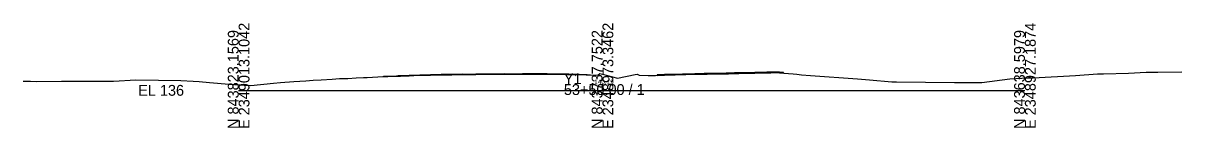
# Model space of a CAD drawing. Extents: x -26 to 2349090, y -10 to 844481.
# Drawn here: x 2300 to 2600, y -9.7 to 17.4 of the extents above; entities that cross this region are included whole.
import ezdxf

# ---------------------------------------------------------------- set-up
doc = ezdxf.new("R2010")
doc.units = 0
for name, color, linetype in [('Exist Cross Section Cell', 7, 'Continuous'), ('Exist XS Center Line Elevation Label', 7, 'Continuous'), ('Exist XS Ground Line', 7, 'Continuous'), ('Prop CMT Pvmt Surface', 7, 'Continuous'), ('Prop XS Earthwork Shape', 7, 'Continuous')]:
    doc.layers.add(name, color=color, linetype=linetype)

msp = doc.modelspace()

# ---------------------------------------------------------------- linework, layer by layer
at = {"layer": 'Exist Cross Section Cell'}
for p, q in [((2355.79, 0), (2450, 0)), ((2450, 0), (2450, 1.6)), ((2450, 0), (2559.37, 0))]:
    msp.add_line(p, q, dxfattribs=at)
at = {"layer": 'Exist XS Ground Line'}
msp.add_lwpolyline([(2300, 2.37), (2301.94, 2.36), (2303.36, 2.33), (2309.93, 2.39), (2311.19, 2.41), (2316.69, 2.37), (2317.92, 2.39), (2323.36, 2.41), (2329.14, 2.73), (2335.04, 2.67), (2340.85, 2.58), (2343.98, 2.38), (2345.54, 2.27), (2348.25, 2.07), (2353.37, 1.57), (2358.94, 1.27), (2364.8, 1.86), (2366.6, 2.06), (2370.08, 2.28), (2373.15, 2.49), (2375.07, 2.63), (2377.18, 2.73), (2380.01, 2.93), (2381.94, 3.03), (2382.69, 3.04), (2383.08, 3.05), (2384.09, 3.07), (2386.23, 3.21), (2388.16, 3.32), (2389.06, 3.35), (2391.87, 3.46), (2394.39, 3.57), (2396.65, 3.66), (2397.13, 3.68), (2397.7, 3.69), (2399.22, 3.74), (2399.91, 3.76), (2401.15, 3.82), (2402.69, 3.89), (2403.7, 3.92), (2405.44, 3.97), (2407.2, 4.01), (2408.2, 4.03), (2409.6, 4.03), (2410.95, 4.04), (2412.41, 4.08), (2413.7, 4.1), (2415.54, 4.1), (2416.44, 4.1), (2417.22, 4.11), (2419.17, 4.15), (2419.56, 4.15), (2421.47, 4.16), (2421.95, 4.16), (2422.36, 4.17), (2424.69, 4.21), (2427.45, 4.18), (2429.31, 4.2), (2430.29, 4.21), (2430.72, 4.21), (2432.52, 4.21), (2432.94, 4.21), (2433.31, 4.21), (2435.7, 4.21), (2437.83, 4.17), (2438.69, 4.16), (2439.19, 4.15), (2440.6, 4.13), (2441.24, 4.12), (2442.94, 4.09), (2443.95, 4.08), (2445.75, 4.02), (2446.85, 4), (2448.81, 3.97), (2449.31, 4.38), (2450, 4.19), (2453.86, 3.13), (2458.46, 4.12), (2458.99, 4.22), (2459.52, 3.96), (2461.8, 3.87), (2462.56, 3.85), (2463.69, 3.86), (2466.05, 3.94), (2468.85, 4.01), (2470.72, 4.06), (2471.58, 4.09), (2473.89, 4.15), (2474.47, 4.16), (2474.8, 4.17), (2476.36, 4.2), (2477.1, 4.21), (2479.08, 4.24), (2479.83, 4.25), (2480.69, 4.27), (2482.01, 4.3), (2482.61, 4.31), (2484.21, 4.36), (2485.34, 4.4), (2485.77, 4.41), (2486.68, 4.42), (2487.67, 4.44), (2488.15, 4.45), (2489.41, 4.48), (2490.85, 4.52), (2491.37, 4.53), (2492.54, 4.55), (2493.27, 4.56), (2493.6, 4.56), (2495.13, 4.58), (2495.81, 4.55), (2499.36, 4.24), (2500.36, 4.15), (2501.55, 4.02), (2503.86, 3.82), (2516, 2.97), (2519.13, 2.71), (2524.92, 2.18), (2525.42, 2.21), (2526.15, 2.17), (2541.13, 1.99), (2548.21, 2.06), (2555.44, 2.98), (2560.09, 3.22), (2561.53, 3.2), (2572.43, 3.88), (2578.14, 4.23), (2579.74, 4.31), (2586.22, 4.46), (2590.77, 4.67), (2593.75, 4.7), (2600, 4.79)], dxfattribs=at)
at = {"layer": 'Prop CMT Pvmt Surface'}
for p, q in [((2393.29, 3.65), (2394.39, 3.7)), ((2393.29, 3.52), (2393.29, 3.65)), ((2394.39, 3.7), (2396.64, 3.78)), ((2396.64, 3.78), (2397.12, 3.8)), ((2397.12, 3.8), (2397.7, 3.82)), ((2397.7, 3.82), (2399.21, 3.86)), ((2399.21, 3.86), (2399.91, 3.89)), ((2399.91, 3.89), (2401.14, 3.94)), ((2401.14, 3.94), (2402.68, 4.01)), ((2402.68, 4.01), (2403.69, 4.04)), ((2403.69, 4.04), (2405.44, 4.09)), ((2405.44, 4.09), (2407.2, 4.14)), ((2407.2, 4.14), (2408.19, 4.16)), ((2408.19, 4.16), (2409.6, 4.16)), ((2409.6, 4.16), (2410.95, 4.17)), ((2410.95, 4.17), (2412.41, 4.2)), ((2412.41, 4.2), (2413.7, 4.23)), ((2413.7, 4.23), (2415.54, 4.22)), ((2415.54, 4.22), (2416.44, 4.22)), ((2416.44, 4.22), (2417.21, 4.24)), ((2417.21, 4.24), (2419.17, 4.28)), ((2419.17, 4.28), (2419.56, 4.28)), ((2419.56, 4.28), (2421.47, 4.29)), ((2421.47, 4.29), (2421.95, 4.29)), ((2421.95, 4.29), (2422.35, 4.3)), ((2422.35, 4.3), (2424.69, 4.34)), ((2424.69, 4.34), (2427.45, 4.31)), ((2427.45, 4.31), (2429.31, 4.32)), ((2429.31, 4.32), (2430.29, 4.33)), ((2430.29, 4.33), (2430.72, 4.34)), ((2430.72, 4.34), (2432.52, 4.34)), ((2432.52, 4.34), (2432.94, 4.34)), ((2432.94, 4.34), (2433.32, 4.34)), ((2433.32, 4.34), (2435.7, 4.33)), ((2435.7, 4.33), (2437.83, 4.3)), ((2437.83, 4.3), (2438.69, 4.28)), ((2438.69, 4.28), (2439.2, 4.28)), ((2439.2, 4.28), (2440.6, 4.25)), ((2440.6, 4.25), (2441.24, 4.25)), ((2441.24, 4.25), (2442.94, 4.22)), ((2442.94, 4.22), (2443.96, 4.21)), ((2443.96, 4.21), (2445.76, 4.14)), ((2445.76, 4.14), (2446, 4.14)), ((2446, 4.14), (2446, 4.01)), ((2464.15, 4), (2466.04, 4.06)), ((2464.15, 4), (2464.15, 3.88)), ((2466.04, 4.06), (2468.85, 4.13)), ((2468.85, 4.13), (2470.72, 4.19)), ((2470.72, 4.19), (2471.58, 4.21)), ((2471.58, 4.21), (2473.88, 4.27)), ((2473.88, 4.27), (2474.46, 4.29)), ((2474.46, 4.29), (2474.79, 4.29)), ((2474.79, 4.29), (2476.36, 4.32)), ((2476.36, 4.32), (2477.1, 4.33)), ((2477.1, 4.33), (2479.08, 4.36)), ((2479.08, 4.36), (2479.82, 4.37)), ((2479.82, 4.37), (2480.69, 4.39)), ((2480.69, 4.39), (2482.01, 4.42)), ((2482.01, 4.42), (2482.6, 4.44)), ((2482.6, 4.44), (2484.2, 4.49)), ((2484.2, 4.49), (2485.34, 4.52)), ((2485.34, 4.52), (2485.76, 4.53)), ((2485.76, 4.53), (2486.67, 4.55)), ((2486.67, 4.55), (2487.67, 4.56)), ((2487.67, 4.56), (2488.15, 4.57)), ((2488.15, 4.57), (2489.4, 4.61)), ((2489.4, 4.61), (2490.85, 4.64)), ((2490.85, 4.64), (2491.37, 4.65)), ((2491.37, 4.65), (2492.54, 4.67)), ((2492.54, 4.67), (2493.26, 4.68)), ((2493.26, 4.68), (2493.6, 4.69)), ((2493.6, 4.69), (2495.13, 4.7)), ((2495.13, 4.7), (2495.82, 4.68)), ((2495.82, 4.68), (2496.88, 4.58)), ((2496.88, 4.46), (2496.88, 4.58))]:
    msp.add_line(p, q, dxfattribs=at)
at = {"layer": 'Prop XS Earthwork Shape'}
for points in [[(2397.12, 3.8), (2397.7, 3.82), (2399.21, 3.86), (2399.91, 3.89), (2401.14, 3.94), (2402.68, 4.01), (2403.69, 4.04), (2405.44, 4.09), (2407.2, 4.14), (2408.19, 4.16), (2409.6, 4.16), (2410.95, 4.17), (2412.41, 4.2), (2413.7, 4.23), (2415.54, 4.22), (2416.44, 4.22), (2417.21, 4.24), (2419.17, 4.28), (2419.56, 4.28), (2421.47, 4.29), (2421.95, 4.29), (2422.35, 4.3), (2424.69, 4.34), (2427.45, 4.31), (2429.31, 4.32), (2430.29, 4.33), (2430.72, 4.34), (2432.52, 4.34), (2432.94, 4.34), (2433.32, 4.34), (2435.7, 4.33), (2437.83, 4.3), (2438.69, 4.28), (2439.2, 4.28), (2440.6, 4.25), (2441.24, 4.25), (2442.94, 4.22), (2443.96, 4.21), (2445.76, 4.14), (2446, 4.14), (2446, 4.01), (2445.75, 4.02), (2443.95, 4.08), (2442.94, 4.09), (2441.24, 4.12), (2440.6, 4.13), (2439.19, 4.15), (2438.69, 4.16), (2437.83, 4.17), (2435.7, 4.21), (2433.31, 4.21), (2432.94, 4.21), (2432.52, 4.21), (2430.72, 4.21), (2430.29, 4.21), (2429.31, 4.2), (2427.45, 4.18), (2424.69, 4.21), (2422.36, 4.17), (2421.95, 4.16), (2421.47, 4.16), (2419.56, 4.15), (2419.17, 4.15), (2417.22, 4.11), (2416.44, 4.1), (2415.54, 4.1), (2413.7, 4.1), (2412.41, 4.08), (2410.95, 4.04), (2409.6, 4.03), (2408.2, 4.03), (2407.2, 4.01), (2405.44, 3.97), (2403.7, 3.92), (2402.69, 3.89), (2401.15, 3.82), (2399.91, 3.76), (2399.22, 3.74), (2397.7, 3.69), (2397.13, 3.68), (2396.65, 3.66), (2394.39, 3.57), (2393.29, 3.52), (2393.29, 3.65), (2394.39, 3.7), (2396.64, 3.78)], [(2496.88, 4.46), (2496.88, 4.58), (2495.82, 4.68), (2495.13, 4.7), (2493.6, 4.69), (2493.26, 4.68), (2492.54, 4.67), (2491.37, 4.65), (2490.85, 4.64), (2489.4, 4.61), (2488.15, 4.57), (2487.67, 4.56), (2486.67, 4.55), (2485.76, 4.53), (2485.34, 4.52), (2484.2, 4.49), (2482.6, 4.44), (2482.01, 4.42), (2480.69, 4.39), (2479.82, 4.37), (2479.08, 4.36), (2477.1, 4.33), (2476.36, 4.32), (2474.79, 4.29), (2474.46, 4.29), (2473.88, 4.27), (2471.58, 4.21), (2470.72, 4.19), (2468.85, 4.13), (2466.04, 4.06), (2464.15, 4), (2464.15, 3.88), (2466.05, 3.94), (2468.85, 4.01), (2470.72, 4.06), (2471.58, 4.09), (2473.89, 4.15), (2474.47, 4.16), (2474.8, 4.17), (2476.36, 4.2), (2477.1, 4.21), (2479.08, 4.24), (2479.83, 4.25), (2480.69, 4.27), (2482.01, 4.3), (2482.61, 4.31), (2484.21, 4.36), (2485.34, 4.4), (2485.77, 4.41), (2486.68, 4.42), (2487.67, 4.44), (2488.15, 4.45), (2489.41, 4.48), (2490.85, 4.52), (2491.37, 4.53), (2492.54, 4.55), (2493.27, 4.56), (2493.6, 4.56), (2495.13, 4.58), (2495.81, 4.55)]]:
    msp.add_lwpolyline(points, close=True, dxfattribs=at)

# ---------------------------------------------------------------- texts
at = {"layer": 'Exist Cross Section Cell'}
for s, p in [('N 843823.1569', (2355.79, -10)), ('E 2349013.1042', (2358.59, -10)), ('N 843737.7522', (2450, -10)), ('E 2348973.3462', (2452.8, -10)), ('N 843638.5979', (2559.37, -10)), ('E 2348927.1874', (2562.17, -10))]:
    msp.add_text(s, height=2.8, rotation=90, dxfattribs=at).set_placement(p)
for s, p in [('Y1', (2440, 1.6)), ('EL 136', (2329.79, -1.4)), ('53+50.00 / 1', (2440, -1.2))]:
    msp.add_text(s, height=2.8, dxfattribs=at).set_placement(p)
at = {"layer": 'Exist XS Center Line Elevation Label'}
msp.add_text('140.19', height=1.2, dxfattribs=at).set_placement((2447.85, 1.59))

doc.saveas('drawing.dxf')
